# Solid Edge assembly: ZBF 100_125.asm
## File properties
Title: Zylinder
Author: bmolnar
Template: iso metric assembly.asm
Last saved by: bmolnar
Revision: 25
Application: Solid Edge
Username: bmolnar
Dokumentum tartalom típus: 1
Document Number: ZBF 100/125
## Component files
Profilrohr.par
Kolbenstange.par
Mutter.par
Kit.par
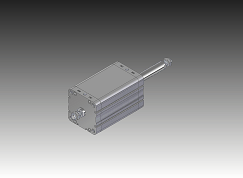
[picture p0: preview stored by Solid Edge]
